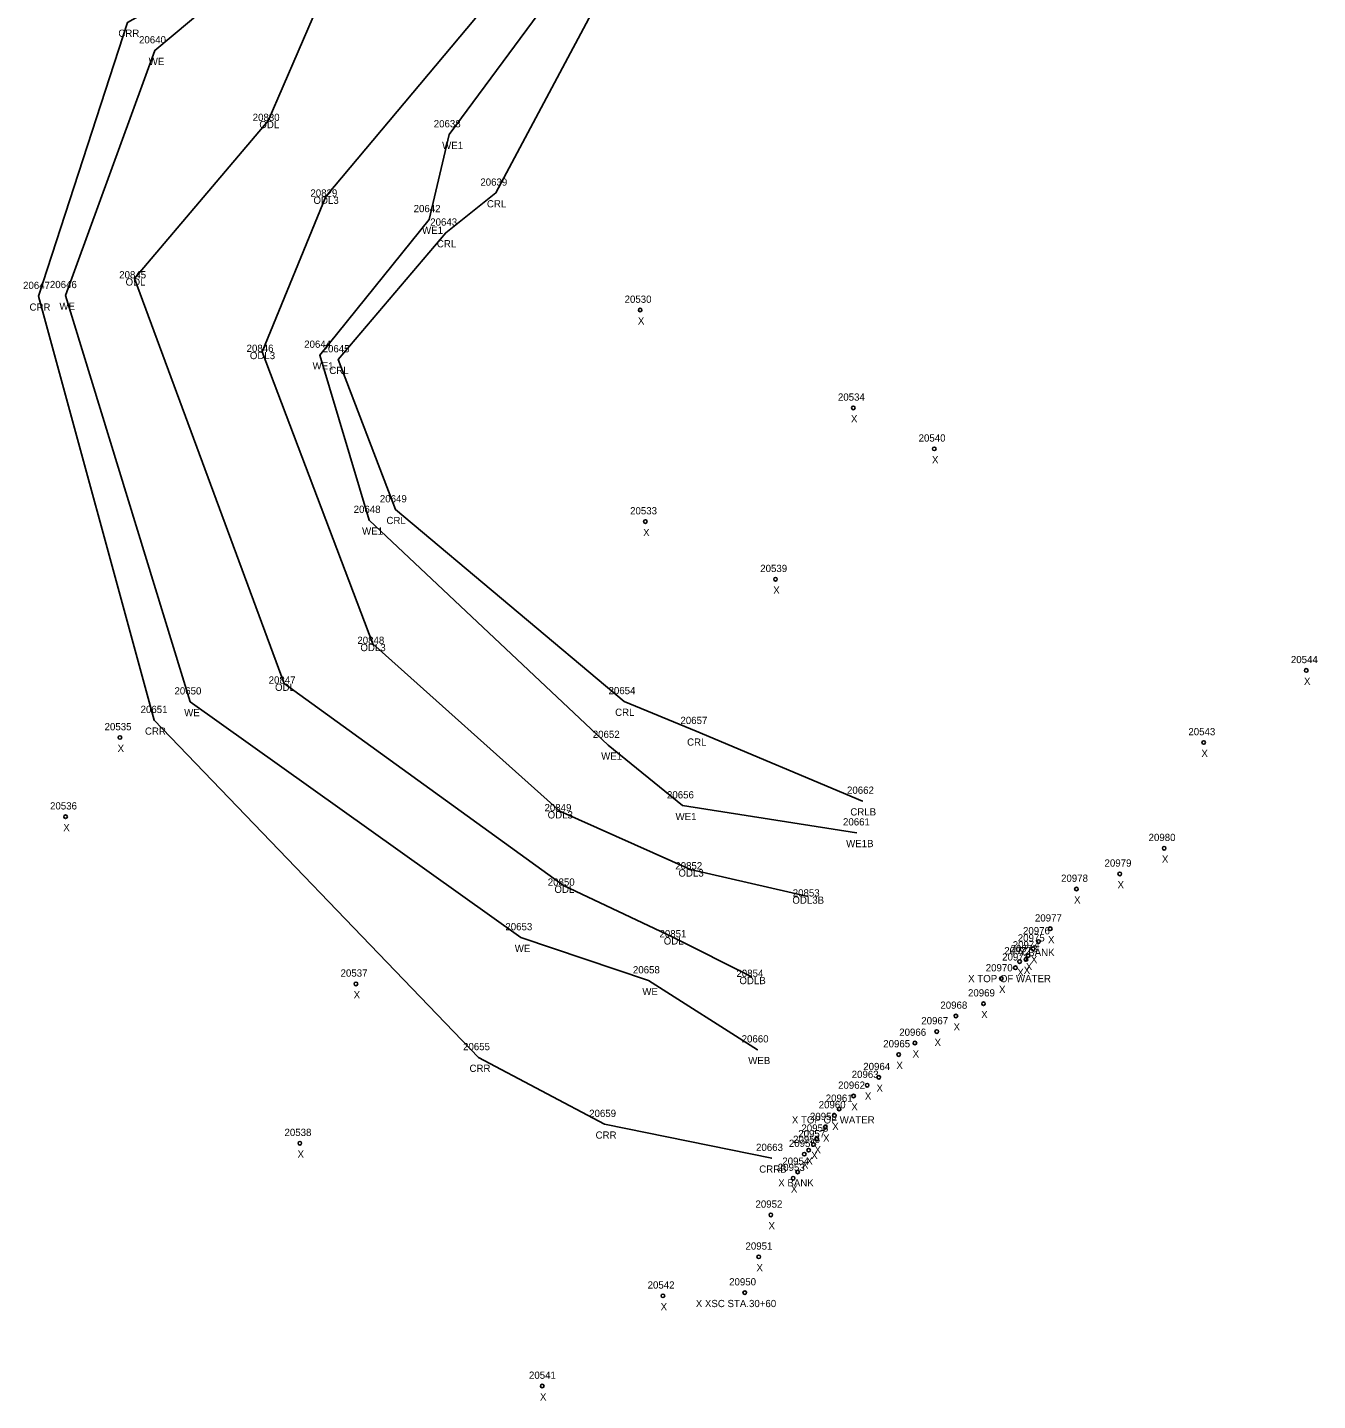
# Model space of a CAD drawing. Extents: x 1966740 to 1969291, y 1117378 to 1118461.
# Drawn here: x 1967713.5 to 1967891.8, y 1117420.7 to 1117610.5 of the extents above; entities that cross this region are included whole.
import ezdxf

# ---------------------------------------------------------------- set-up
doc = ezdxf.new("R2010")
doc.units = 0
for name, color, linetype in [('RD_EX_H2O', 7, 'Continuous'), ('RD_EX_H2O_txCode', 7, 'Continuous'), ('RD_SMD_Locator', 7, 'Continuous'), ('RD_SMD_Misc', 7, 'Continuous')]:
    doc.layers.add(name, color=color, linetype=linetype)

msp = doc.modelspace()

# ---------------------------------------------------------------- linework, layer by layer
at = {"layer": 'RD_EX_H2O'}
for points in [[(1967837.87, 1118086.59), (1967816.35, 1118042.52), (1967807.65, 1118000.54), (1967802.25, 1117964.95), (1967802.7, 1117929.05), (1967808.24, 1117891.66), (1967818.1, 1117847.27), (1967841.92, 1117812.91), (1967830.83, 1117773.47), (1967807.55, 1117730.13), (1967792.1, 1117688.21), (1967759.2, 1117626.42), (1967746.8, 1117597.58), (1967728.31, 1117575.82), (1967748.97, 1117519.79), (1967787.59, 1117491.86), (1967802.7, 1117484.72), (1967813.63, 1117479.24)], [(1967846.86, 1118079.71), (1967831.29, 1118034.88), (1967818.84, 1117997.76), (1967815.72, 1117964.67), (1967820.18, 1117928.06), (1967829.19, 1117896.79), (1967834.11, 1117854.1), (1967863.47, 1117815.02), (1967842.32, 1117765.95), (1967826.02, 1117725.1), (1967807.77, 1117682.35), (1967775.42, 1117611.81), (1967754.74, 1117587.12), (1967745.94, 1117565.65), (1967761.23, 1117525.28), (1967787.1, 1117502.15), (1967805.18, 1117494.11), (1967821.41, 1117490.36)], [(1967794.3, 1117875.45), (1967796.63, 1117853.43), (1967809.67, 1117835.4), (1967828.83, 1117808.28), (1967805.08, 1117754.56), (1967786.33, 1117708.04), (1967780.19, 1117689.35), (1967762.68, 1117651.19), (1967736.39, 1117616.3), (1967727.33, 1117611.21), (1967715.04, 1117573.35), (1967731.01, 1117514.73), (1967775.86, 1117468.11), (1967793.29, 1117458.88), (1967816.39, 1117454.18)], [(1967873.55, 1117813.3), (1967873.54, 1117810.73), (1967868.98, 1117791.48), (1967856.29, 1117756.05), (1967834.78, 1117721.72), (1967815.36, 1117678.52), (1967799.96, 1117628.39), (1967778.25, 1117587.63), (1967771.33, 1117582.11), (1967756.46, 1117564.6), (1967764.36, 1117543.85), (1967795.97, 1117517.33), (1967805.92, 1117513.21), (1967828.95, 1117503.56)], [(1967870.38, 1117810.73), (1967864.06, 1117791.33), (1967853.89, 1117756.14), (1967832.83, 1117722.61), (1967813.26, 1117679.41), (1967797.31, 1117630.26), (1967771.82, 1117595.7), (1967769.03, 1117583.97), (1967753.91, 1117565.22), (1967760.74, 1117542.39), (1967793.79, 1117511.28), (1967804.07, 1117502.92), (1967828.12, 1117499.18)], [(1967837.15, 1117809.04), (1967808.01, 1117752.12), (1967788.48, 1117706.78), (1967783.36, 1117689.17), (1967764.63, 1117648.93), (1967738.42, 1117613.44), (1967731.11, 1117607.31), (1967718.77, 1117573.47), (1967736.01, 1117517.29), (1967781.71, 1117484.69), (1967799.34, 1117478.73), (1967814.43, 1117469.18)]]:
    msp.add_lwpolyline(points, dxfattribs=at)
at = {"layer": 'RD_SMD_Locator'}
for centre, radius in [((1967731.11, 1117607.31), 0.001), ((1967746.8, 1117597.58), 0.001), ((1967771.82, 1117595.7), 0.001), ((1967754.74, 1117587.12), 0.001), ((1967778.25, 1117587.63), 0.001), ((1967769.03, 1117583.97), 0.001), ((1967771.33, 1117582.11), 0.001), ((1967728.31, 1117575.82), 0.001), ((1967715.04, 1117573.35), 0.001), ((1967718.77, 1117573.47), 0.001), ((1967798.2, 1117571.44), 0.25), ((1967745.94, 1117565.65), 0.001), ((1967753.91, 1117565.22), 0.001), ((1967756.46, 1117564.6), 0.001), ((1967827.66, 1117557.91), 0.25), ((1967838.85, 1117552.25), 0.25), ((1967760.74, 1117542.39), 0.001), ((1967764.36, 1117543.85), 0.001), ((1967798.92, 1117542.19), 0.25), ((1967816.91, 1117534.22), 0.25), ((1967761.23, 1117525.28), 0.001), ((1967890.27, 1117521.62), 0.25), ((1967748.97, 1117519.79), 0.001), ((1967736.01, 1117517.29), 0.001), ((1967795.97, 1117517.33), 0.001), ((1967731.01, 1117514.73), 0.001), ((1967726.29, 1117512.34), 0.25), ((1967805.92, 1117513.21), 0.001), ((1967876.1, 1117511.65), 0.25), ((1967793.79, 1117511.28), 0.001), ((1967804.07, 1117502.92), 0.001), ((1967828.95, 1117503.56), 0.001), ((1967718.78, 1117501.39), 0.25), ((1967787.1, 1117502.15), 0.001), ((1967828.12, 1117499.18), 0.001), ((1967870.63, 1117497.03), 0.25), ((1967805.18, 1117494.11), 0.001), ((1967864.5, 1117493.49), 0.25), ((1967787.59, 1117491.86), 0.001), ((1967858.5, 1117491.39), 0.25), ((1967821.41, 1117490.36), 0.001), ((1967854.89, 1117485.9), 0.25), ((1967781.71, 1117484.69), 0.001), ((1967802.7, 1117484.72), 0.001), ((1967852.52, 1117483.14), 0.25), ((1967853.26, 1117484.13), 0.25), ((1967850.65, 1117481.37), 0.25), ((1967851.53, 1117481.66), 0.25), ((1967851.82, 1117482.18), 0.25), ((1967850.07, 1117480.51), 0.25), ((1967758.91, 1117478.28), 0.25), ((1967799.34, 1117478.73), 0.001), ((1967813.63, 1117479.24), 0.001), ((1967848.13, 1117479.01), 0.25), ((1967845.66, 1117475.54), 0.25), ((1967841.84, 1117473.84), 0.25), ((1967836.18, 1117470.1), 0.25), ((1967839.2, 1117471.69), 0.25), ((1967814.43, 1117469.18), 0.001), ((1967833.94, 1117468.51), 0.25), ((1967775.86, 1117468.11), 0.001), ((1967829.58, 1117464.27), 0.25), ((1967831.18, 1117465.36), 0.25), ((1967827.7, 1117462.78), 0.25), ((1967825.71, 1117460.98), 0.25), ((1967793.29, 1117458.88), 0.001), ((1967823.79, 1117458.46), 0.25), ((1967825.06, 1117460.08), 0.25), ((1967822.61, 1117456.85), 0.25), ((1967751.16, 1117456.25), 0.25), ((1967820.88, 1117454.74), 0.25), ((1967821.49, 1117455.29), 0.25), ((1967822.17, 1117456.07), 0.25), ((1967816.39, 1117454.18), 0.001), ((1967819.35, 1117451.41), 0.25), ((1967819.97, 1117452.27), 0.25), ((1967816.26, 1117446.34), 0.25), ((1967814.59, 1117440.54), 0.25), ((1967801.34, 1117435.15), 0.25), ((1967812.66, 1117435.59), 0.25), ((1967784.67, 1117422.68), 0.25)]:
    msp.add_circle(centre, radius, dxfattribs=at)

# ---------------------------------------------------------------- texts
at = {"layer": 'RD_EX_H2O_txCode'}
for s, p in [('CRR', (1967726.07, 1117609.21)), ('20640', (1967728.93, 1117608.31)), ('WE', (1967730.27, 1117605.31)), ('20830', (1967744.64, 1117597.58)), ('ODL', (1967745.56, 1117596.58)), ('20638', (1967769.67, 1117596.7)), ('WE1', (1967770.83, 1117593.7)), ('20829', (1967752.62, 1117587.12)), ('20639', (1967776.11, 1117588.63)), ('ODL3', (1967753.04, 1117586.12)), ('20642', (1967766.89, 1117584.97)), ('CRL', (1967777.02, 1117585.63)), ('20643', (1967769.18, 1117583.11)), ('WE1', (1967768.05, 1117581.97)), ('CRL', (1967770.1, 1117580.11)), ('20845', (1967726.19, 1117575.82)), ('20647', (1967712.9, 1117574.35)), ('20646', (1967716.61, 1117574.47)), ('ODL', (1967727.07, 1117574.82)), ('CRR', (1967713.79, 1117571.35)), ('WE', (1967717.93, 1117571.47)), ('20644', (1967751.76, 1117566.22)), ('20846', (1967743.8, 1117565.65)), ('ODL3', (1967744.25, 1117564.65)), ('20645', (1967754.31, 1117565.6)), ('WE1', (1967752.92, 1117563.22)), ('CRL', (1967755.23, 1117562.6)), ('20648', (1967758.6, 1117543.39)), ('20649', (1967762.22, 1117544.85)), ('CRL', (1967763.13, 1117541.85)), ('WE1', (1967759.76, 1117540.39)), ('20848', (1967759.11, 1117525.28)), ('ODL3', (1967759.53, 1117524.28)), ('20847', (1967746.85, 1117519.79)), ('ODL', (1967747.73, 1117518.79)), ('20650', (1967733.83, 1117518.29)), ('20654', (1967793.83, 1117518.33)), ('20651', (1967729.15, 1117515.73)), ('WE', (1967735.17, 1117515.29)), ('CRL', (1967794.74, 1117515.33)), ('CRR', (1967729.75, 1117512.73)), ('20657', (1967803.77, 1117514.21)), ('20652', (1967791.65, 1117512.28)), ('CRL', (1967804.69, 1117511.21)), ('WE1', (1967792.81, 1117509.28)), ('20656', (1967801.91, 1117503.92)), ('20662', (1967826.79, 1117504.56)), ('20849', (1967784.98, 1117502.15)), ('CRLB', (1967827.25, 1117501.56)), ('ODL3', (1967785.41, 1117501.15)), ('WE1', (1967803.09, 1117500.92)), ('20661', (1967826.24, 1117500.18)), ('WE1B', (1967826.67, 1117497.18)), ('20852', (1967803.06, 1117494.11)), ('20850', (1967785.43, 1117491.86)), ('ODL3', (1967803.49, 1117493.11)), ('ODL', (1967786.35, 1117490.86)), ('20853', (1967819.29, 1117490.36)), ('ODL3B', (1967819.24, 1117489.36)), ('20653', (1967779.57, 1117485.69)), ('20851', (1967800.87, 1117484.72)), ('WE', (1967780.87, 1117482.69)), ('ODL', (1967801.46, 1117483.72)), ('20658', (1967797.2, 1117479.73)), ('20854', (1967811.51, 1117479.24)), ('WE', (1967798.5, 1117476.73)), ('ODLB', (1967811.92, 1117478.24)), ('20655', (1967773.72, 1117469.11)), ('20660', (1967812.23, 1117470.18)), ('WEB', (1967813.14, 1117467.18)), ('CRR', (1967774.61, 1117466.11)), ('20659', (1967791.15, 1117459.88)), ('CRR', (1967792.04, 1117456.88)), ('20663', (1967814.22, 1117455.18)), ('CRRB', (1967814.66, 1117452.18))]:
    msp.add_text(s, height=1, dxfattribs=at).set_placement(p)
at = {"layer": 'RD_SMD_Misc'}
for s, p in [('20530', (1967796.05, 1117572.44)), ('X', (1967797.89, 1117569.44)), ('20534', (1967825.54, 1117558.91)), ('X', (1967827.34, 1117555.91)), ('20540', (1967836.69, 1117553.25)), ('X', (1967838.54, 1117550.25)), ('20533', (1967796.81, 1117543.19)), ('X', (1967798.61, 1117540.19)), ('20539', (1967814.8, 1117535.22)), ('X', (1967816.6, 1117532.22)), ('20544', (1967888.15, 1117522.62)), ('X', (1967889.96, 1117519.62)), ('20535', (1967724.17, 1117513.34)), ('20543', (1967873.98, 1117512.65)), ('X', (1967725.97, 1117510.34)), ('X', (1967875.78, 1117509.65)), ('20536', (1967716.63, 1117502.39)), ('X', (1967718.46, 1117499.39)), ('20980', (1967868.48, 1117498.03)), ('20979', (1967862.39, 1117494.49)), ('X', (1967870.32, 1117495.03)), ('20978', (1967856.38, 1117492.39)), ('X', (1967864.19, 1117491.49)), ('X', (1967858.18, 1117489.39)), ('20977', (1967852.77, 1117486.9)), ('20976', (1967851.12, 1117485.13)), ('20972', (1967848.53, 1117482.37)), ('20973', (1967849.41, 1117482.66)), ('20974', (1967849.7, 1117483.18)), ('20975', (1967850.4, 1117484.14)), ('X', (1967854.58, 1117483.9)), ('20971', (1967848.24, 1117481.51)), ('X BANK', (1967850.58, 1117482.13)), ('X', (1967852.2, 1117481.14)), ('20537', (1967756.79, 1117479.28)), ('20970', (1967845.97, 1117480.01)), ('X', (1967850.33, 1117479.37)), ('X', (1967851.22, 1117479.66)), ('X', (1967851.51, 1117480.18)), ('X TOP OF WATER', (1967843.54, 1117478.51)), ('X', (1967847.81, 1117477.01)), ('X', (1967758.6, 1117476.28)), ('20968', (1967839.7, 1117474.84)), ('20969', (1967843.52, 1117476.54)), ('X', (1967845.34, 1117473.54)), ('20966', (1967834.01, 1117471.1)), ('20967', (1967837.06, 1117472.69)), ('X', (1967841.52, 1117471.84)), ('20965', (1967831.8, 1117469.51)), ('X', (1967838.89, 1117469.69)), ('X', (1967835.86, 1117468.1)), ('20963', (1967827.44, 1117465.27)), ('20964', (1967829.04, 1117466.36)), ('X', (1967833.62, 1117466.51)), ('20962', (1967825.56, 1117463.78)), ('X', (1967830.87, 1117463.36)), ('20961', (1967823.85, 1117461.98)), ('X', (1967829.26, 1117462.27)), ('20960', (1967822.88, 1117461.08)), ('X', (1967827.39, 1117460.78)), ('X TOP OF WATER', (1967819.17, 1117458.98)), ('20958', (1967820.49, 1117457.85)), ('20959', (1967821.67, 1117459.46)), ('X', (1967824.75, 1117458.08)), ('20538', (1967749.04, 1117457.25)), ('20956', (1967819.34, 1117456.29)), ('20957', (1967820.05, 1117457.07)), ('X', (1967823.48, 1117456.46)), ('X', (1967750.84, 1117454.25)), ('20955', (1967818.76, 1117455.74)), ('X', (1967821.85, 1117454.07)), ('X', (1967822.3, 1117454.85)), ('20953', (1967817.23, 1117452.41)), ('20954', (1967817.85, 1117453.27)), ('X', (1967820.56, 1117452.74)), ('X', (1967821.17, 1117453.29)), ('X BANK', (1967817.29, 1117450.27)), ('X', (1967819.04, 1117449.41)), ('20952', (1967814.14, 1117447.34)), ('X', (1967815.94, 1117444.34)), ('20951', (1967812.76, 1117441.54)), ('X', (1967814.28, 1117438.54)), ('20542', (1967799.23, 1117436.15)), ('20950', (1967810.5, 1117436.59)), ('X', (1967801.03, 1117433.15)), ('X XSC STA.30+60', (1967805.89, 1117433.59)), ('20541', (1967782.83, 1117423.68)), ('X', (1967784.35, 1117420.68))]:
    msp.add_text(s, height=1, dxfattribs=at).set_placement(p)

doc.saveas('drawing.dxf')
